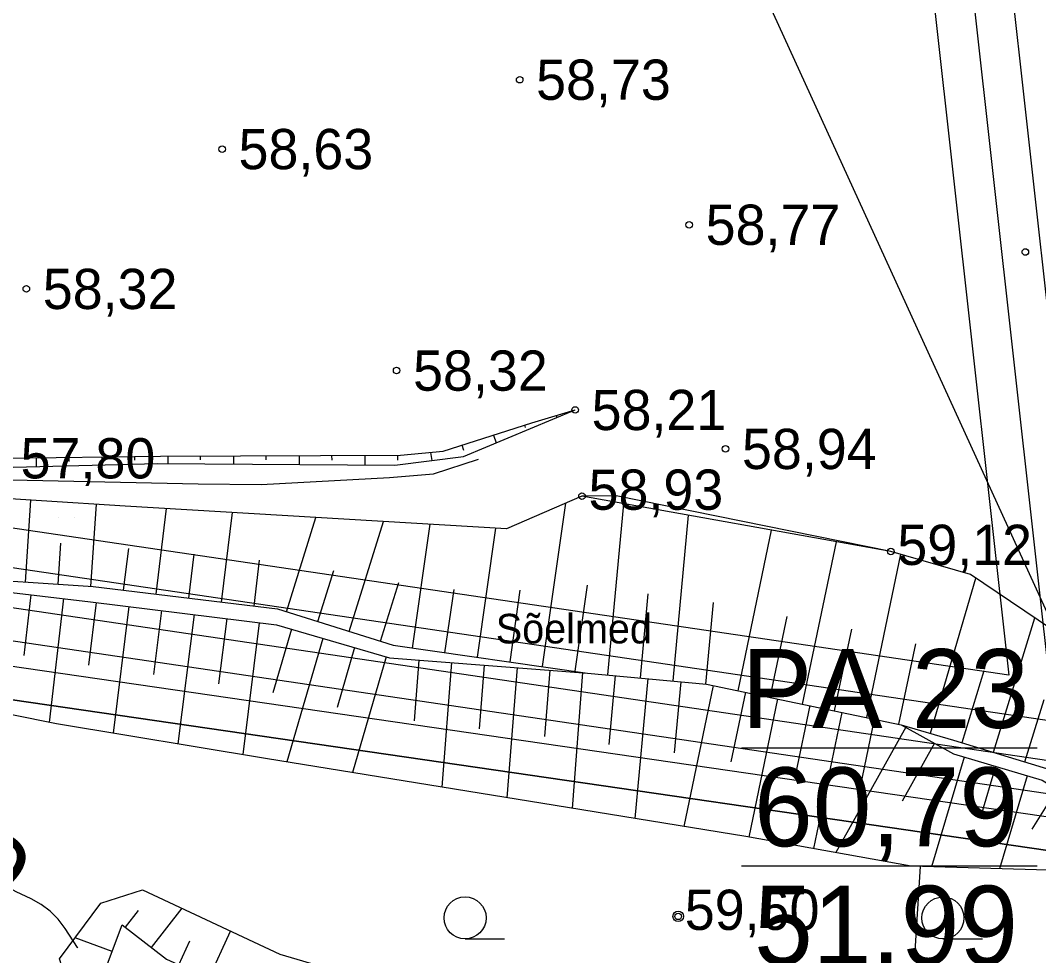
# Model space of a CAD drawing. Extents: x 532503 to 539665, y 6557663 to 6561526.
# Drawn here: x 535438.1 to 535500.1, y 6559502.2 to 6559559.2 of the extents above; entities that cross this region are included whole.
import ezdxf

# ---------------------------------------------------------------- set-up
doc = ezdxf.new("R2010")
doc.units = 0
for name, color, linetype in [('Default', 7, 'Continuous'), ('GEOLPUNKT', 7, 'Continuous'), ('HALJASTUS', 7, 'Continuous'), ('HORISONTAAL-EH2000', 7, 'Continuous'), ('illumineerimisjooned', 7, 'Continuous'), ('kataster', 7, 'Continuous'), ('KORGUS-EH2000', 7, 'Continuous'), ('Lõige', 7, 'Continuous'), ('ME_aktiivne', 7, 'Continuous'), ('Plokid', 7, 'Continuous'), ('RELJEEF', 7, 'Continuous'), ('TM_aktiivne', 7, 'Continuous')]:
    doc.layers.add(name, color=color, linetype=linetype)

# ---------------------------------------------------------------- blocks, each defined once
blk = doc.blocks.new('POINT_DISPLAY')
at = {"layer": 'Default'}
blk.add_line((0, 0), (0, 0), dxfattribs=at)

msp = doc.modelspace()

# ---------------------------------------------------------------- linework, layer by layer
at = {"layer": 'GEOLPUNKT'}
for p, q in [((535482.03, 6559514.89), (535500.03, 6559514.89)), ((535482.03, 6559507.69), (535500.03, 6559507.69))]:
    msp.add_line(p, q, dxfattribs=at)
at = {"layer": 'HALJASTUS'}
for p, q in [((535465.205, 6559503.25), (535467.605, 6559503.25)), ((535494.285, 6559503.247), (535496.685, 6559503.247))]:
    msp.add_line(p, q, dxfattribs=at)
for centre in [(535465.205, 6559504.53), (535494.285, 6559504.527)]:
    msp.add_circle(centre, 1.28, dxfattribs=at)
at = {"layer": 'HORISONTAAL-EH2000'}
for points in [[(535495.591, 6559498.47), (535492.597, 6559502.5), (535492.917, 6559507.664)], [(535441.636, 6559502.699), (535441.62, 6559502.723), (535440.869, 6559503.891), (535440.441, 6559504.446), (535439.961, 6559504.942), (535439.405, 6559505.349), (535438.797, 6559505.698), (535437.893, 6559506.119), (535437.699, 6559506.214), (535437.507, 6559506.315), (535437.32, 6559506.423), (535437.135, 6559506.536), (535436.963, 6559506.663), (535436.802, 6559506.803), (535436.66, 6559506.961), (535436.53, 6559507.131), (535436.486, 6559507.196)]]:
    msp.add_lwpolyline(points, dxfattribs=at)
at = {"layer": 'illumineerimisjooned'}
msp.add_lwpolyline([(535537.644, 6559868.04), (535535.932, 6559811.278), (535531.57, 6559735.34), (535531.4, 6559680.476), (535535.969, 6559621.33), (535541.688, 6559571.196), (535546.449, 6559503.997), (535276.396, 6559543.285), (535107.957, 6559502.648), (535182.405, 6559686.245), (535250.294, 6559648.566)], close=True, dxfattribs=at)
msp.add_lwpolyline([(535476.016, 6559817.954), (535471.557, 6559803.013), (535503.755, 6559513.648), (535136.963, 6559567.806)], dxfattribs=at)
at = {"layer": 'kataster'}
for points in [[(535538.05, 6559871.58), (535539.27, 6559872.49), (535541.59, 6559874.28), (535537.93, 6559811.19), (535533.57, 6559735.28), (535533.4, 6559680.55), (535537.96, 6559621.52), (535543.68, 6559571.38), (535548.62, 6559501.66), (535276.49, 6559541.25), (535104.64, 6559499.79), (535181.52, 6559689.04), (535250.3, 6559650.84), (535504.86, 6559846.09)], [(535276.49, 6559541.25), (535548.62, 6559501.66), (535550.5, 6559476.8), (535550.75, 6559439.7), (535556.1, 6559391), (535571.15, 6559343.15), (535576.2, 6559317.65), (535584.3, 6559293.5), (535605.6, 6559242.75), (535617.25, 6559223.1), (535609.75, 6559220.15), (535573.85, 6559205.3), (535547.45, 6559197.5), (535476, 6559183.4), (535417.7, 6559171.6), (535375.95, 6559160.8), (535349.75, 6559155.9), (535338.01, 6559156.08), (535318.85, 6559280.76)]]:
    msp.add_lwpolyline(points, close=True, dxfattribs=at)
at = {"layer": 'KORGUS-EH2000'}
for centre, radius in [((535468.528, 6559555.553), 0.2), ((535450.418, 6559551.33), 0.2), ((535478.844, 6559546.724), 0.2), ((535499.302, 6559545.064), 0.2), ((535438.504, 6559542.817), 0.2), ((535461.039, 6559537.845), 0.2), ((535471.904, 6559535.449), 0.2), ((535481.056, 6559533.077), 0.2), ((535472.32, 6559530.198), 0.2), ((535491.11, 6559526.838), 0.2), ((535478.175, 6559504.622), 0.32), ((535478.175, 6559504.622), 0.2)]:
    msp.add_circle(centre, radius, dxfattribs=at)
at = {"layer": 'Lõige'}
msp.add_lwpolyline([(535150.705, 6560087.504), (535159.93, 6560069.75), (535218.82, 6559968.7), (535305.655, 6559887.851), (535461.67, 6559608.38), (535506.03, 6559511.29), (535514.367, 6559493.043)], dxfattribs=at)
at = {"layer": 'ME_aktiivne'}
msp.add_lwpolyline([(535181.4, 6559689.09), (535250.12, 6559650.95), (535250.5, 6559651.24), (535480.86, 6559827.19), (535473.59, 6559802.83), (535506.03, 6559511.29), (535131.71, 6559566.56)], close=True, dxfattribs=at)
at = {"layer": 'Plokid'}
for points in [[(535471.605, 6559811.564), (535469.118, 6559803.232), (535501.026, 6559516.477), (535140.335, 6559569.734)], [(535468.361, 6559809.086), (535466.679, 6559803.451), (535498.296, 6559519.306), (535141.263, 6559572.023)]]:
    msp.add_lwpolyline(points, dxfattribs=at)
at = {"layer": 'RELJEEF'}
for p, q in [((535470.756, 6559535.112), (535470.794, 6559534.985)), ((535471.904, 6559535.449), (535471.904, 6559535.449)), ((535468.891, 6559534.375), (535468.841, 6559534.537)), ((535466.938, 6559533.921), (535467.093, 6559533.44)), ((535465.125, 6559532.981), (535465.035, 6559533.306)), ((535439.105, 6559532.534), (535439.112, 6559531.998)), ((535441.109, 6559532.306), (535441.105, 6559532.561)), ((535443.105, 6559532.588), (535443.111, 6559532.105)), ((535445.108, 6559532.387), (535445.105, 6559532.616)), ((535447.105, 6559532.639), (535447.108, 6559532.19)), ((535449.106, 6559532.411), (535449.105, 6559532.647)), ((535451.105, 6559532.655), (535451.107, 6559532.158)), ((535453.106, 6559532.403), (535453.104, 6559532.664)), ((535455.104, 6559532.672), (535455.107, 6559532.126)), ((535457.106, 6559532.395), (535457.104, 6559532.681)), ((535459.104, 6559532.689), (535459.107, 6559532.094)), ((535461.117, 6559532.402), (535461.104, 6559532.697)), ((535463.097, 6559532.862), (535463.174, 6559532.365)), ((535438.445, 6559524.972), (535438.775, 6559529.962)), ((535442.436, 6559524.708), (535442.767, 6559529.71)), ((535446.408, 6559524.234), (535447.041, 6559529.448)), ((535469.922, 6559519.826), (535471.344, 6559529.775)), ((535473.889, 6559519.32), (535474.859, 6559529.744)), ((535450.379, 6559523.752), (535451.041, 6559529.208)), ((535454.328, 6559523.17), (535456.132, 6559528.903)), ((535477.871, 6559518.95), (535478.81, 6559529.037)), ((535458.144, 6559521.969), (535460.248, 6559528.656)), ((535462.002, 6559520.957), (535463.078, 6559528.487)), ((535465.962, 6559520.391), (535467.085, 6559528.246)), ((535481.821, 6559518.36), (535483.861, 6559528.134)), ((535440.441, 6559524.84), (535440.606, 6559527.338)), ((535444.423, 6559524.475), (535444.732, 6559527.022)), ((535485.737, 6559517.543), (535487.8, 6559527.43)), ((535448.394, 6559523.993), (535448.717, 6559526.661)), ((535452.364, 6559523.512), (535452.703, 6559526.3)), ((535489.652, 6559516.726), (535491.725, 6559526.661)), ((535456.236, 6559522.569), (535457.213, 6559525.675)), ((535493.532, 6559515.766), (535496.298, 6559525.214)), ((535460.051, 6559521.369), (535461.179, 6559524.951)), ((535463.982, 6559520.674), (535464.532, 6559524.52)), ((535467.942, 6559520.109), (535468.566, 6559524.476)), ((535471.901, 6559519.543), (535472.649, 6559524.774)), ((535438.785, 6559524.198), (535438.357, 6559520.509)), ((535440.772, 6559523.967), (535439.897, 6559516.422)), ((535442.758, 6559523.734), (535442.282, 6559519.913)), ((535475.88, 6559519.135), (535476.357, 6559524.263)), ((535479.863, 6559518.764), (535480.324, 6559523.724)), ((535444.743, 6559523.487), (535443.781, 6559515.766)), ((535446.728, 6559523.24), (535446.242, 6559519.34)), ((535448.712, 6559522.992), (535447.731, 6559515.116)), ((535450.697, 6559522.745), (535450.202, 6559518.768)), ((535452.682, 6559522.498), (535451.681, 6559514.466)), ((535483.779, 6559517.952), (535484.805, 6559522.867)), ((535497.362, 6559514.61), (535499.877, 6559522.795)), ((535454.636, 6559522.103), (535453.507, 6559518.227)), ((535487.695, 6559517.135), (535488.732, 6559522.106)), ((535456.556, 6559521.544), (535454.367, 6559514.026)), ((535458.476, 6559520.985), (535457.416, 6559517.344)), ((535491.61, 6559516.317), (535492.632, 6559521.212)), ((535460.397, 6559520.426), (535458.345, 6559513.377)), ((535462.383, 6559520.228), (535462.097, 6559516.52)), ((535464.377, 6559520.074), (535463.791, 6559512.489)), ((535466.371, 6559519.92), (535466.072, 6559516.043)), ((535468.365, 6559519.767), (535467.753, 6559511.843)), ((535470.359, 6559519.613), (535470.047, 6559515.566)), ((535472.353, 6559519.459), (535471.715, 6559511.198)), ((535495.45, 6559515.197), (535496.797, 6559519.582)), ((535474.345, 6559519.278), (535473.955, 6559515.088)), ((535476.336, 6559519.093), (535475.544, 6559510.578)), ((535478.328, 6559518.907), (535477.925, 6559514.583)), ((535480.312, 6559518.675), (535478.522, 6559510.096)), ((535482.27, 6559518.267), (535481.384, 6559514.021)), ((535484.228, 6559517.858), (535482.474, 6559509.453)), ((535499.273, 6559514.022), (535500.441, 6559517.824)), ((535486.186, 6559517.449), (535485.314, 6559513.275)), ((535488.143, 6559517.041), (535486.413, 6559508.746)), ((535490.101, 6559516.632), (535489.242, 6559512.513)), ((535492.025, 6559516.133), (535487.769, 6559508.503)), ((535493.772, 6559515.158), (535491.811, 6559511.644)), ((535495.575, 6559514.319), (535493.595, 6559507.644)), ((535497.493, 6559513.75), (535496.578, 6559510.667)), ((535499.41, 6559513.181), (535497.731, 6559507.524)), ((535501.212, 6559512.356), (535499.701, 6559509.933)), ((535444.537, 6559503.961), (535445.33, 6559504.977)), ((535446.113, 6559502.73), (535447.98, 6559505.119)), ((535443.72, 6559502.475), (535441.483, 6559503.325)), ((535449.609, 6559500.834), (535450.931, 6559503.731)), ((535447.79, 6559501.664), (535448.455, 6559503.123))]:
    msp.add_line(p, q, dxfattribs=at)
for points in [[(535297.878, 6559556.991), (535300.955, 6559560.202), (535304.863, 6559562.851), (535308.464, 6559563.893), (535316.166, 6559565.474), (535321.978, 6559566.57), (535326.353, 6559566.065), (535336.33, 6559561.796), (535345.815, 6559558.237), (535351.649, 6559557.426), (535358.035, 6559557.197), (535366.847, 6559556.781), (535373.695, 6559555.113), (535380.943, 6559549.946), (535390.022, 6559543.772), (535398.525, 6559539.938), (535409.207, 6559536.123), (535420.047, 6559534.51), (535429.637, 6559532.62), (535437.724, 6559531.961), (535446.481, 6559532.195), (535460.922, 6559532.08), (535465.102, 6559532.609), (535471.904, 6559535.449)], [(535357.213, 6559558.325), (535365.84, 6559558.362), (535372.67, 6559556.85), (535375.971, 6559555.031), (535380.701, 6559551.803), (535386.43, 6559547.158), (535390.476, 6559544.2), (535395.25, 6559542.551), (535401.18, 6559540.222), (535409.288, 6559537.284), (535414.775, 6559536.623), (535422.012, 6559534.642), (535425.471, 6559534.078), (535437.154, 6559532.507), (535446.678, 6559532.637), (535461.281, 6559532.698), (535463.878, 6559532.932), (535469.262, 6559534.673), (535471.904, 6559535.449)], [(535346.711, 6559556.549), (535362.712, 6559555.757), (535370.123, 6559554.969), (535374.193, 6559553.047), (535380.636, 6559548.805), (535386.213, 6559544.485), (535391.02, 6559542.134), (535399.357, 6559538.44), (535405.849, 6559535.971), (535410.291, 6559534.827), (535418.382, 6559533.685), (535427.027, 6559531.781), (535436.649, 6559531.224), (535448.97, 6559530.947), (535452.802, 6559530.911), (535460.597, 6559531.342), (535463.291, 6559531.557), (535466.015, 6559532.449)], [(535444.51, 6559529.6), (535434.314, 6559530.243), (535428.476, 6559529.173), (535415.388, 6559532.65), (535405.445, 6559531.791), (535398.44, 6559532.383), (535386.176, 6559535.293), (535382.008, 6559537.119), (535381.295, 6559541.748), (535379.057, 6559547.967), (535377.411, 6559550.091), (535370.401, 6559554.053), (535364.171, 6559554.679), (535354.268, 6559555.06)], [(535374.645, 6559531.517), (535379.751, 6559531.046), (535386.596, 6559528.882), (535395.248, 6559527.413), (535404.407, 6559526.868), (535410.5, 6559527), (535414.866, 6559526.668), (535423.744, 6559525.025), (535433.967, 6559524.757), (535442.414, 6559523.777), (535453.728, 6559522.368), (535460.606, 6559520.365), (535472.647, 6559519.436), (535479.902, 6559518.761), (535491.744, 6559516.29), (535494.936, 6559514.509), (535500.324, 6559512.91), (535505.499, 6559509.683), (535509.231, 6559509.806), (535514.574, 6559508.932), (535522.49, 6559506.722), (535533.276, 6559504.867), (535539.834, 6559503.851)], [(535374.645, 6559531.517), (535379.751, 6559531.046), (535386.596, 6559528.882), (535395.248, 6559527.413), (535404.407, 6559526.868), (535410.5, 6559527), (535414.866, 6559526.668), (535423.744, 6559525.025), (535433.967, 6559524.757), (535442.414, 6559523.777), (535453.728, 6559522.368), (535460.606, 6559520.365), (535472.647, 6559519.436), (535479.902, 6559518.761), (535491.744, 6559516.29), (535494.936, 6559514.509), (535500.324, 6559512.91), (535505.499, 6559509.683), (535509.231, 6559509.806), (535514.574, 6559508.932), (535522.49, 6559506.722), (535533.276, 6559504.867), (535539.834, 6559503.851)], [(535537.792, 6559502.337), (535540.19, 6559502.516), (535542.7, 6559503.43), (535542.649, 6559505.395), (535540.506, 6559505.4), (535534.849, 6559507.683), (535522.747, 6559512.003), (535513.573, 6559516.537), (535504.773, 6559519.096), (535501.699, 6559521.564), (535495.96, 6559525.442), (535491.11, 6559526.838), (535472.32, 6559530.198), (535467.723, 6559528.208), (535444.51, 6559529.6)], [(535537.792, 6559502.337), (535540.19, 6559502.516), (535542.7, 6559503.43), (535542.649, 6559505.395), (535540.506, 6559505.4), (535534.849, 6559507.683), (535522.747, 6559512.003), (535513.573, 6559516.537), (535504.773, 6559519.096), (535501.699, 6559521.564), (535495.96, 6559525.442), (535491.11, 6559526.838), (535474.406, 6559530.213), (535472.32, 6559530.198), (535467.723, 6559528.208)], [(535537.792, 6559502.337), (535531.511, 6559502.794), (535512.556, 6559504.792), (535505.257, 6559507.384), (535501.366, 6559507.418), (535492.353, 6559507.68), (535482.281, 6559509.488), (535470.679, 6559511.366), (535453.05, 6559514.241), (535440.336, 6559516.333), (535419.279, 6559520.588), (535409.082, 6559523.167), (535390.613, 6559524.675), (535375.928, 6559527.87), (535369.333, 6559527.721), (535359.717, 6559529.37)], [(535537.792, 6559502.337), (535531.511, 6559502.794), (535512.556, 6559504.792), (535505.257, 6559507.384), (535501.366, 6559507.418), (535492.353, 6559507.68), (535482.281, 6559509.488), (535470.679, 6559511.366), (535453.05, 6559514.241), (535440.336, 6559516.333), (535419.279, 6559520.588), (535409.082, 6559523.167), (535390.613, 6559524.675), (535375.928, 6559527.87), (535369.333, 6559527.721), (535359.717, 6559529.37)], [(535467.723, 6559528.208), (535444.51, 6559529.6)], [(535404.407, 6559526.868), (535410.203, 6559527.847), (535414.8, 6559528.293), (535423.956, 6559525.766), (535434.015, 6559525.265), (535442.579, 6559524.699), (535453.793, 6559523.338), (535460.822, 6559521.126), (535472.647, 6559519.436)], [(535404.407, 6559526.868), (535410.203, 6559527.847), (535414.8, 6559528.293), (535423.956, 6559525.766), (535434.015, 6559525.265), (535442.579, 6559524.699), (535453.793, 6559523.338), (535460.822, 6559521.126), (535472.647, 6559519.436)], [(535491.744, 6559516.29), (535494.939, 6559515.354), (535500.851, 6559513.538), (535505.714, 6559512.578), (535509.249, 6559510.866), (535514.574, 6559508.932)], [(535491.744, 6559516.29), (535494.939, 6559515.354), (535500.851, 6559513.538), (535505.714, 6559512.578), (535509.249, 6559510.866), (535514.574, 6559508.932)], [(535441.242, 6559499.796), (535440.531, 6559502.037), (535443.039, 6559505.429), (535445.583, 6559506.246), (535453.922, 6559502.324), (535462.807, 6559499.708), (535470.109, 6559496.57), (535471.559, 6559490.599), (535470.709, 6559488.832), (535465.03, 6559487.036), (535459.674, 6559488.196), (535452.248, 6559492.939), (535444.639, 6559497.583), (535441.242, 6559499.796)], [(535443.438, 6559501.732), (535444.342, 6559504.114), (535447.036, 6559502.008), (535456.722, 6559497.587), (535462.335, 6559495.78), (535467.512, 6559494.607), (535467.231, 6559492.477), (535460.411, 6559492.831)], [(535443.438, 6559501.732), (535444.342, 6559504.114), (535447.036, 6559502.008), (535456.722, 6559497.587), (535462.335, 6559495.78), (535467.512, 6559494.607), (535467.231, 6559492.477), (535460.411, 6559492.831)]]:
    msp.add_lwpolyline(points, dxfattribs=at)
msp.add_lwpolyline([(535441.242, 6559499.796), (535440.531, 6559502.037), (535443.039, 6559505.429), (535445.583, 6559506.246), (535453.922, 6559502.324), (535462.807, 6559499.708), (535470.109, 6559496.57), (535471.559, 6559490.599), (535470.709, 6559488.832), (535465.03, 6559487.036), (535459.674, 6559488.196), (535452.248, 6559492.939), (535444.639, 6559497.583)], close=True, dxfattribs=at)
at = {"layer": 'TM_aktiivne'}
msp.add_lwpolyline([(535539.77, 6559872.18), (535537.93, 6559811.19), (535533.57, 6559735.28), (535533.4, 6559680.55), (535537.96, 6559621.52), (535543.68, 6559571.38), (535548.62, 6559501.66), (535276.49, 6559541.25), (535104.64, 6559499.79), (535181.4, 6559689.09), (535250.12, 6559650.95)], close=True, dxfattribs=at)

# ---------------------------------------------------------------- block references
at = {"layer": 'RELJEEF'}
for p in [(535440.433, 6559528.9), (535441.412, 6559528.9), (535484.349, 6559515.59), (535487.667, 6559515.59), (535488.646, 6559515.59)]:
    msp.add_blockref('POINT_DISPLAY', p, dxfattribs=at)

# ---------------------------------------------------------------- texts
at = {"layer": 'GEOLPUNKT'}
for s, p in [('PA 23', (535482.048, 6559516.09)), ('60,79', (535482.791, 6559508.89)), ('51,99', (535482.791, 6559501.69))]:
    msp.add_text(s, height=4.8, dxfattribs=at).set_placement(p)
at = {"layer": 'HORISONTAAL-EH2000'}
msp.add_text('59', height=4.8, rotation=312.15706, dxfattribs=at).set_placement((535430.908, 6559509.781))
at = {"layer": 'KORGUS-EH2000'}
for s, p in [('58,73 ', (535469.528, 6559554.328)), ('58,63 ', (535451.418, 6559550.105)), ('58,77 ', (535479.844, 6559545.499)), ('58,32 ', (535439.504, 6559541.592)), ('58,32 ', (535462.039, 6559536.62)), ('58,21 ', (535472.904, 6559534.224)), ('58,94 ', (535482.056, 6559531.852)), ('57,80 ', (535438.154, 6559531.282)), ('58,93 ', (535472.72, 6559529.373)), ('59,12 ', (535491.51, 6559526.013)), ('59,60 ', (535478.575, 6559503.797))]:
    msp.add_text(s, height=2.45, dxfattribs=at).set_placement(p)
at = {"layer": 'RELJEEF'}
msp.add_text('Sõelmed', height=1.8, dxfattribs=at).set_placement((535467.074, 6559521.237))

doc.saveas('drawing.dxf')
